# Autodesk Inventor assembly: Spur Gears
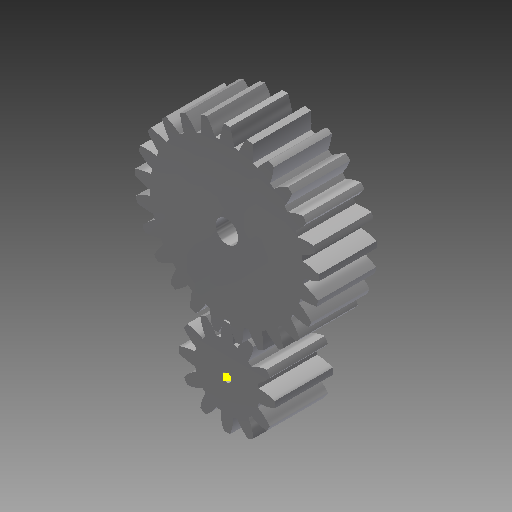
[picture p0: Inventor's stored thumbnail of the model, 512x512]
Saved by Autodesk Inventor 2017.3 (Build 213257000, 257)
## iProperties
Created: 2020-03
Part Number: Spur Gears
Document SubType Name: Assembly
Designer: Tim_G
Categories: <?xml version="1.0" encoding="UTF-16"?> <MemberInstance><Categories><FamilyTemplate/><ParamToTemplateMap><ParamToTemplate><ParamToTemplate CategoryParameter="//
ClientObjectVersion: 1
Author: Tim_G
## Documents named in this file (3)
- C:\Users\Tim_G\OneDrive - McMaster University\Documents\Documents\Books\McMaster First Year Courses\Winter Engineering 1C03\Project\Project Files (Prosthetic Frame Assembly)\Hand Assembly\Design Accelerator\Spur Gears1.iam
- C:\Users\Tim_G\OneDrive - McMaster University\Documents\Documents\Books\McMaster First Year Courses\Winter Engineering 1C03\Project\Project Files (Prosthetic Frame Assembly)\Hand Assembly\Design Accelerator\Spur Gear11.ipt
- C:\Users\Tim_G\OneDrive - McMaster University\Documents\Documents\Books\McMaster First Year Courses\Winter Engineering 1C03\Project\Project Files (Prosthetic Frame Assembly)\Hand Assembly\Design Accelerator\Spur Gear21.ipt
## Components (2 placed, 2 different names)
1. Spur Gear1:1 — Rotation:1
2. Spur Gear2:1 — Rotation:1
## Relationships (1: RelateRotation 1)
- Rotation:1 [RelateRotation]: Spur Gear1:1 ↔ Spur Gear2:1
